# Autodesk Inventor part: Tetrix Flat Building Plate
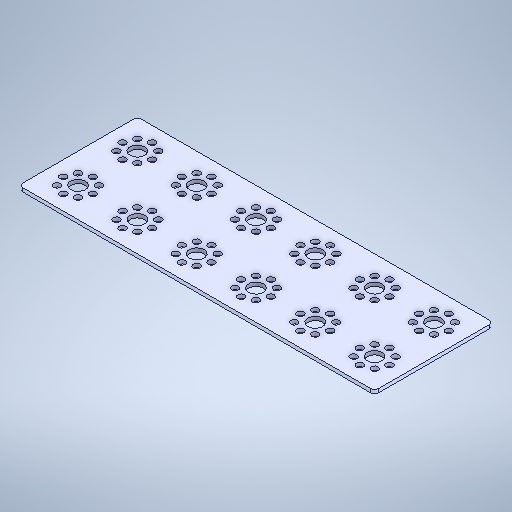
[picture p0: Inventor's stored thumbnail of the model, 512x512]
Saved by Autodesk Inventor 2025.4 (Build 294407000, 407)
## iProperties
Created: 2021-10
Part Number: Tetrix Flat Building Plate
Material: Genérico
Document SubType Name: Modeling
Designer: usuario
Density: 1 g/cm^3
Appearance: Valor por defecto
Author: usuario
Sending System: SolidWorks 2016
Last Author: LENOVO
Last Saved: 2021-10-21
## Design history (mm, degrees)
feature "Boss-Extrude1"
node "Plane1"
node "Sólido1"
